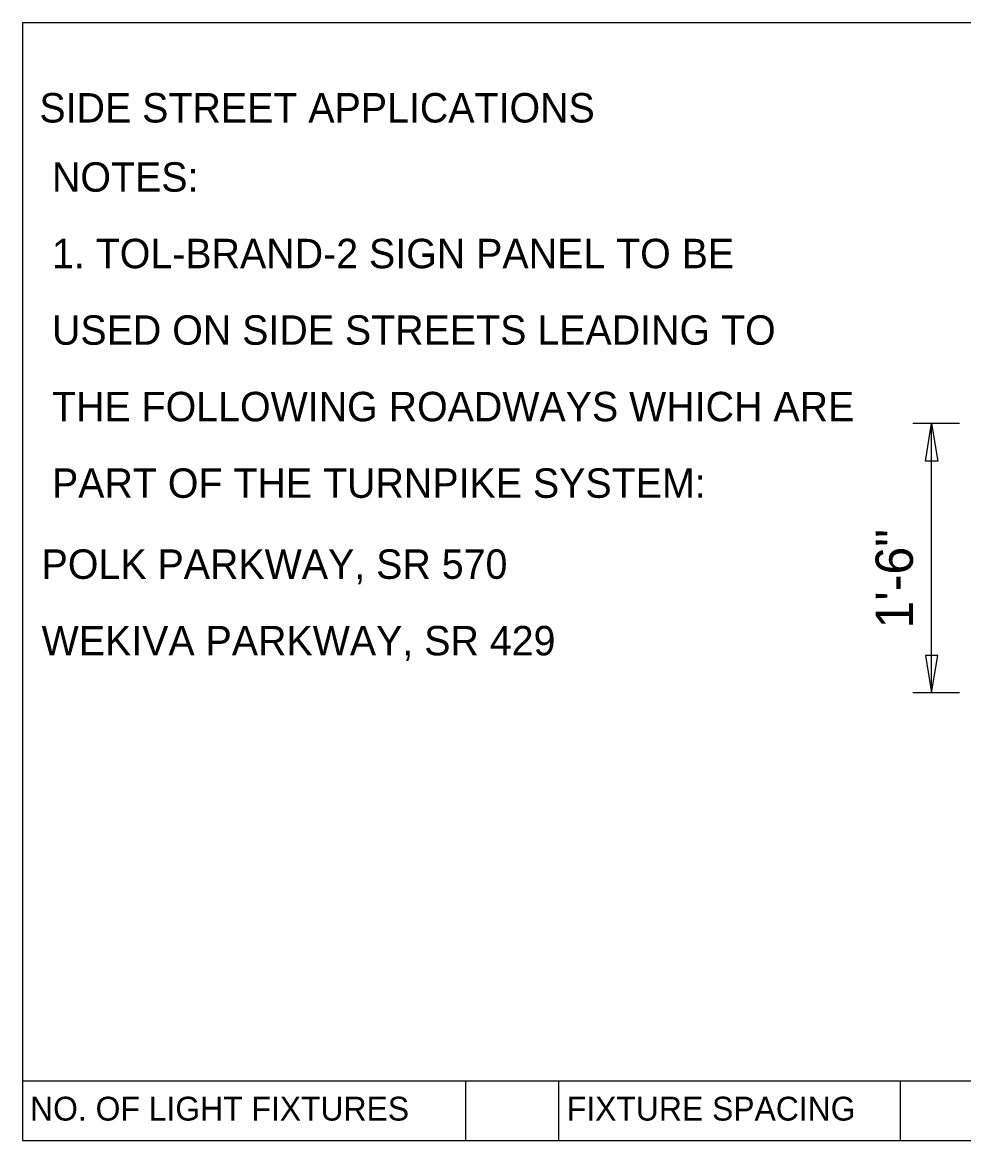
# Model space of a CAD drawing. Extents: x 17890628 to 17890754, y 17897693 to 17897992.
# Drawn here: x 17890694.3 to 17890699.55, y 17897882.4 to 17897888.63 of the extents above; entities that cross this region are included whole.
import ezdxf

# ---------------------------------------------------------------- set-up
doc = ezdxf.new("R2010")
doc.units = 0
for name, color, linetype in [('GSDims', 7, 'Continuous'), ('SheetLinesMisc2_dp', 7, 'Continuous'), ('TextMinor', 7, 'Continuous'), ('TextMisc', 7, 'Continuous')]:
    doc.layers.add(name, color=color, linetype=linetype)

msp = doc.modelspace()

# ---------------------------------------------------------------- linework, layer by layer
at = {"layer": 'GSDims'}
for p, q in [((17890699.5265, 17897886.3987), (17890699.2661, 17897886.3987)), ((17890699.3703, 17897884.8987), (17890699.3703, 17897886.3987)), ((17890699.5265, 17897886.3987), (17890699.5265, 17897886.3987)), ((17890699.5265, 17897884.8987), (17890699.2661, 17897884.8987)), ((17890699.5265, 17897884.8987), (17890699.5265, 17897884.8987))]:
    msp.add_line(p, q, dxfattribs=at)
for points in [[(17890699.3703, 17897886.3987), (17890699.405, 17897886.1904), (17890699.3356, 17897886.1904)], [(17890699.3703, 17897884.8987), (17890699.405, 17897885.107), (17890699.3356, 17897885.107)]]:
    msp.add_lwpolyline(points, close=True, dxfattribs=at)
at = {"layer": 'SheetLinesMisc2_dp'}
for p, q in [((17890694.3026, 17897888.6344), (17890707.0939, 17897888.6344)), ((17890694.3026, 17897888.6344), (17890694.3026, 17897882.4127)), ((17890694.3026, 17897882.7378), (17890707.0939, 17897882.7378)), ((17890696.7733, 17897882.7378), (17890696.7733, 17897882.4039)), ((17890697.291, 17897882.7378), (17890697.291, 17897882.4039)), ((17890699.1957, 17897882.7378), (17890699.1957, 17897882.4039)), ((17890694.3026, 17897882.4127), (17890694.3026, 17897882.4043)), ((17890694.3026, 17897882.4039), (17890707.0939, 17897882.4039))]:
    msp.add_line(p, q, dxfattribs=at)

# ---------------------------------------------------------------- texts
at = {"layer": 'GSDims'}
msp.add_text('1\'-6"', height=0.20833, rotation=90, dxfattribs=at).set_placement((17890699.2661, 17897885.2568))
at = {"layer": 'TextMinor'}
for s, p in [('NO. OF LIGHT FIXTURES', (17890694.3456, 17897882.5157)), ('FIXTURE SPACING', (17890697.337, 17897882.5157))]:
    msp.add_text(s, height=0.132863, dxfattribs=at).set_placement(p)
at = {"layer": 'TextMisc'}
for s, height, p in [('SIDE STREET APPLICATIONS', 0.164001, (17890694.3975, 17897888.0765)), ('NOTES:', 0.164, (17890694.4676, 17897887.691)), ('1. TOL-BRAND-2 SIGN PANEL TO BE', 0.164001, (17890694.4676, 17897887.2646)), ('USED ON SIDE STREETS LEADING TO', 0.164001, (17890694.4676, 17897886.8382)), ('THE FOLLOWING ROADWAYS WHICH ARE', 0.164001, (17890694.4676, 17897886.4118)), ('PART OF THE TURNPIKE SYSTEM:', 0.164001, (17890694.4676, 17897885.9854)), ('POLK PARKWAY, SR 570', 0.164001, (17890694.4098, 17897885.534)), ('WEKIVA PARKWAY, SR 429', 0.164001, (17890694.4098, 17897885.1076))]:
    msp.add_text(s, height=height, dxfattribs=at).set_placement(p)

doc.saveas('drawing.dxf')
